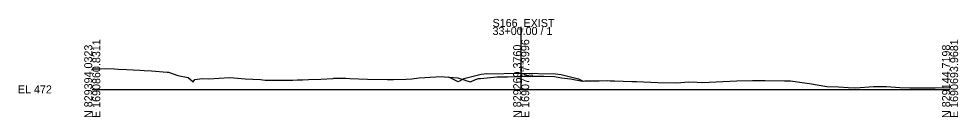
# Model space of a CAD drawing. Extents: x 1621104 to 1621433, y 1192880 to 1199414.
# Drawn here: x 1621104.2 to 1621432.7, y 1198379.5 to 1198413.8 of the extents above; entities that cross this region are included whole.
import ezdxf

# ---------------------------------------------------------------- set-up
doc = ezdxf.new("R2010")
doc.units = 0
for name, color, linetype in [('RD_GPK_XS_Cell', 7, 'Continuous'), ('RD_XS_EarthShd', 7, 'Continuous'), ('RD_XS_ExGround', 7, 'Continuous'), ('RD_XS_Pave', 7, 'Continuous'), ('RD_XS_TieSlope', 7, 'Continuous'), ('RD_XS_TX_Elev_EX', 7, 'Continuous'), ('RD_XS_TX_Elev_PR', 7, 'Continuous')]:
    doc.layers.add(name, color=color, linetype=linetype)

msp = doc.modelspace()

# ---------------------------------------------------------------- linework, layer by layer
at = {"layer": 'RD_GPK_XS_Cell'}
for p, q in [((1621279.86, 1198389.24), (1621279.86, 1198411)), ((1621129.86, 1198389.24), (1621279.86, 1198389.24)), ((1621279.86, 1198389.24), (1621429.86, 1198389.24))]:
    msp.add_line(p, q, dxfattribs=at)
at = {"layer": 'RD_XS_EarthShd'}
for p, q in [((1621267.86, 1198394.61), (1621265.86, 1198394.45)), ((1621291.86, 1198394.61), (1621293.86, 1198394.45))]:
    msp.add_line(p, q, dxfattribs=at)
at = {"layer": 'RD_XS_ExGround'}
msp.add_lwpolyline([(1621129.86, 1198396.38), (1621132.56, 1198396.45), (1621134.35, 1198396.49), (1621137.63, 1198396.4), (1621138.94, 1198396.26), (1621141.89, 1198396.21), (1621146.45, 1198395.94), (1621148.01, 1198395.86), (1621150.54, 1198395.66), (1621156.07, 1198395.29), (1621156.51, 1198395.27), (1621159.76, 1198394.05), (1621163.38, 1198393.36), (1621165.11, 1198391.91), (1621165.77, 1198392.66), (1621168.25, 1198393.03), (1621170.67, 1198392.93), (1621177.91, 1198393.39), (1621179.39, 1198393.28), (1621183.31, 1198392.96), (1621188.69, 1198392.68), (1621190.35, 1198392.39), (1621197.2, 1198392.45), (1621200.02, 1198392.47), (1621201.58, 1198392.52), (1621202.49, 1198392.52), (1621203.38, 1198392.51), (1621205.43, 1198392.63), (1621209.78, 1198392.81), (1621214.06, 1198393.06), (1621214.37, 1198393.09), (1621215.65, 1198393.11), (1621218.54, 1198393.19), (1621219.89, 1198392.99), (1621226.12, 1198392.82), (1621233.11, 1198392.66), (1621234.13, 1198392.64), (1621235.19, 1198392.65), (1621239.6, 1198392.82), (1621241.59, 1198392.96), (1621244.18, 1198393.3), (1621250, 1198393.56), (1621252.14, 1198393.67), (1621253.07, 1198393.63), (1621257.67, 1198393.3), (1621260.24, 1198392.47), (1621260.55, 1198392.36), (1621261.71, 1198392), (1621262.09, 1198391.91), (1621263.94, 1198392.64), (1621264.94, 1198393.01), (1621265.68, 1198393.06), (1621271.47, 1198393.57), (1621275.09, 1198393.62), (1621278.07, 1198393.69), (1621279.86, 1198393.78), (1621280.95, 1198393.83), (1621281.29, 1198393.84), (1621281.98, 1198393.85), (1621285.53, 1198393.81), (1621287.73, 1198393.89), (1621291.46, 1198393.74), (1621293.98, 1198393.31), (1621297.16, 1198392.88), (1621301.28, 1198392.09), (1621302.14, 1198392.17), (1621307.08, 1198392.21), (1621309.89, 1198392.3), (1621311, 1198392.26), (1621312.55, 1198392.25), (1621318.51, 1198391.98), (1621320.24, 1198392.02), (1621327.69, 1198391.65), (1621334.31, 1198391.5), (1621338.47, 1198391.88), (1621341.37, 1198391.74), (1621343.13, 1198391.63), (1621355.28, 1198392.17), (1621360.76, 1198392.38), (1621365.15, 1198392.31), (1621372, 1198392.22), (1621374.06, 1198392.16), (1621379.77, 1198391.4), (1621380.65, 1198391.27), (1621386.75, 1198390.28), (1621390.89, 1198390.07), (1621394.18, 1198389.86), (1621396.93, 1198389.8), (1621403.11, 1198390.21), (1621404.89, 1198390.23), (1621407.63, 1198390.2), (1621412.27, 1198389.94), (1621415.78, 1198389.78), (1621423.55, 1198389.83), (1621424.06, 1198389.81), (1621424.59, 1198389.82), (1621429.86, 1198389.86)], dxfattribs=at)
at = {"layer": 'RD_XS_Pave'}
for p, q in [((1621267.86, 1198394.61), (1621279.86, 1198394.85)), ((1621279.86, 1198394.85), (1621291.86, 1198394.61))]:
    msp.add_line(p, q, dxfattribs=at)
at = {"layer": 'RD_XS_TieSlope'}
for p, q in [((1621257.78, 1198391.91), (1621254.55, 1198393.52)), ((1621259.86, 1198392.95), (1621257.78, 1198391.91)), ((1621265.86, 1198394.45), (1621259.86, 1198392.95)), ((1621293.86, 1198394.45), (1621299.86, 1198392.95)), ((1621299.86, 1198392.95), (1621301.52, 1198392.11))]:
    msp.add_line(p, q, dxfattribs=at)

# ---------------------------------------------------------------- texts
at = {"layer": 'RD_GPK_XS_Cell'}
for s, p in [('S166_EXIST', (1621269.86, 1198411)), ('33+00.00 / 1', (1621269.86, 1198408.2)), ('EL 472', (1621103.86, 1198387.84))]:
    msp.add_text(s, height=2.8, dxfattribs=at).set_placement(p)
for s, p in [('E 1690860.8311', (1621132.66, 1198379.24)), ('E 1690777.3996', (1621282.66, 1198379.24)), ('E 1690693.9681', (1621432.66, 1198379.24)), ('N 829394.0323', (1621129.86, 1198379.24)), ('N 829269.3760', (1621279.86, 1198379.24)), ('N 829144.7198', (1621429.86, 1198379.24))]:
    msp.add_text(s, height=2.8, rotation=90, dxfattribs=at).set_placement(p)
at = {"layer": 'RD_XS_TX_Elev_EX'}
msp.add_text('476.54', height=1, dxfattribs=at).set_placement((1621279.76, 1198393.88))
at = {"layer": 'RD_XS_TX_Elev_PR'}
msp.add_text(' 477.61', height=1, rotation=90, dxfattribs=at).set_placement((1621280.86, 1198394.85))

doc.saveas('drawing.dxf')
